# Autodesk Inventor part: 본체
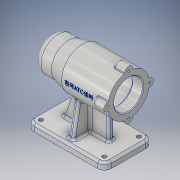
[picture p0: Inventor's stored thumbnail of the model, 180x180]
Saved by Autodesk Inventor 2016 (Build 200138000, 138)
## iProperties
Created: 2019-07
Part Number: 본체
Material: 알루미늄 6061
Document SubType Name: Modeling
Designer: 605-06
Density: 2.7 g/cm^3
Appearance: 알루미늄 - 평지
Mass: 644.654 g
Surface Area: 654.647 cm^2
Volume: 238.761 cm^3
Author: 605-06
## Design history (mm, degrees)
sketch "스케치1"
  geometry: L1 (0, 30)-(67, 30); L2 (67, 30)-(87, 25); L3 (87, 25)-(102, 25); L4 (112, 15)-(112, 0); L5 (112, 0)-(106, 0); L6 (106, 0)-(106, 7.5); L7 (103, 10.5)-(103, 10.5); L8 (103, 10.5)-(103, 15.7); L9 (102.7, 16)-(99, 16); L10 (99, 16)-(99, 17.2); L11 (98.7, 17.5)-(81, 17.5); L12 (81, 17.5)-(81, 20.7); L13 (80.7, 21)-(69, 21); L14 (69, 21)-(69, 21); L15 (66, 24)-(18, 24); L16 (15, 21)-(15, 21); L17 (15, 21)-(1, 21); L18 (0, 22)-(0, 30); L19 (157.163, 0)-(-72.767, 0); L20 (1, 21)-(0, 22); A1 r 3 centre (103, 7.5) between (106, 7.5) and (103, 10.5); A2 r 0.3 centre (102.7, 15.7) between (103, 15.7) and (102.7, 16); A3 r 0.3 centre (98.7, 17.2) between (99, 17.2) and (98.7, 17.5); A4 r 0.3 centre (80.7, 20.7) between (81, 20.7) and (80.7, 21); A5 r 3 centre (66, 21) between (69, 21) and (66, 24); A6 r 3 centre (18, 21) between (18, 24) and (15, 21); A7 r 10 centre (102, 15) between (112, 15) and (102, 25); 2 further points
  constraints: 40 end point, 14 point on circle, 14 tangent, 13 perpendicular, 7 centre point, 3 equal radius, 2 horizontal, 2 horizontal alignment, 2 point on line, 2 vertical, 1 parallel, 1 vertical alignment
  dimensions: "d0" = 112 distance between parallel lines of L4 L18; "d2" = 42 diameter of L17 L19; "d3" = 15 distance between parallel lines of L18 L16; "d4" = 48 diameter of L15 L19; "d5" = 54 distance between parallel lines of L16 L14; "d6" = 42 diameter of L13 L19; "d7" = 12 distance between parallel lines of L14 L12; "d8" = 18 distance between parallel lines of L12 L10; "d9" = 4 distance between parallel lines of L10 L8; "d10" = 3 distance between parallel lines of L8 L6; "d11" = 21 diameter of L7 L19; "d12" = 32 diameter of L9 L19; "d13" = 35 diameter of L11 L19; "d14" = 50 diameter of L3 L19; "d15" = 60 diameter of L1 L19; "d16" = 3 radius of A1; "d17" = 0.3 radius of A2; "d18" = 25 distance from line of L2.end L4; "d19" = 45 distance from line of L1.end L4; "d20" = 1 distance of L17.end point (0, 21); "d21" = 45 deg angle of L17 L20; "d22" = 3 radius of A5; "d23" = 10 radius of A7
revolve "회전1" sketch "스케치1" stored, may be unused: angle "d24" = 90 deg
node "작업 평면1"
sketch "스케치2"
  geometry: L1 (-10, -35)-(-102, -35); L2 (-112, -25)-(-112, 25); L3 (-102, 35)-(-10, 35); L4 (0, 25)-(0, -25); L5 (0, 0)-(-89.179, 0); C1 r 3 at (-102, 25); C2 r 3 at (-102, -25); C3 r 3 at (-10, 25); C4 r 3 at (-10, -25); A1 r 10 centre (-102, -25) between (-112, -25) and (-102, -35); A2 r 10 centre (-102, 25) between (-102, 35) and (-112, 25); A3 r 10 centre (-10, 25) between (0, 25) and (-10, 35); A4 r 10 centre (-10, -25) between (-10, -35) and (0, -25); 1 further point
  constraints: 10 end point, 8 centre point, 8 point on circle, 8 tangent, 4 coincident, 3 equal radius, 2 horizontal, 2 parallel, 2 point on line, 1 perpendicular, 1 vertical alignment
  dimensions: "d26" = 35 distance between parallel lines of L3 L5; "d27" = 70 distance between parallel lines of L1 L3; "d28" = 112 distance between parallel lines of L4 L2; "d29" = 10 radius of A1; "d30" = 6 diameter of C1; "d31" = 6 diameter of C2; "d32" = 6 diameter of C3; "d33" = 6 diameter of C4
extrude "돌출1" join sketch "스케치2" distance "d34" = 10; taper "d35" = 0 deg
sketch "스케치3"
  geometry: L1 (25, -26.691)-(25, -70); L2 (10, -70)-(102, -70) reference; L3 (92, -70)-(76.52, -27.468); L4 (0, -80)-(0, -70) reference; L5 (112, -80)-(112, -70) reference; L6 (112, -70)-(102, -70) reference; L7 (25, -26.691)-(65.86, -26.691); L8 (65.86, -26.691)-(75.023, -23.356); L9 (75.023, -23.356)-(76.52, -27.468); L10 (92, -70)-(25, -70); 1 further point
  constraints: 12 end point, 2 point on line, 1 collinear, 1 horizontal, 1 perpendicular, 1 vertical
  dimensions: "d36" = 25 distance between parallel lines of L4 L1; "d37" = 20 distance from line of L5 L3.start; "d38" = 110 deg angle of L6 L3
extrude "돌출2" join sketch "스케치3" stored distance "d39" = 8; taper "d40" = 0 deg
node "작업 평면2"
sketch "스케치4"
  geometry: L1 (35, -70)-(25, -70) reference; L2 (28, -70)-(19.547, -22.061); L3 (35, -80)-(35, -70) reference; L4 (-28, -70)-(-19.278, -20.537); L5 (-35, -80)-(-35, -70) reference; L6 (-25, -70)-(-35, -70) reference; L7 (-28, -70)-(28, -70); L8 (28, -80)-(28, -70) reference; 1 further point
  constraints: 6 end point, 2 point on line, 1 perpendicular
  dimensions: "d42" = 7 distance from line of L3 L2.start; "d43" = 100 deg angle of L1 L2; "d44" = 7 distance from line of L5 L4.start; "d45" = 100 deg angle of L4 L6
feature "리브1" sketch "스케치4" dims "d46" = 1, "d47" = 8, "d48" = 0, "d49" = 0, "d50" = 1, "d51" = 1
chamfer "모따기1" distance "d52" = 3; stored, may be unused: second distance "d53" = 2, angle "d54" = 45 deg
sketch "스케치5"
  geometry: C1 r 6 at (-30, 0); C2 r 6 at (0, 30); C3 r 6 at (30, 0); C4 r 6 at (0, -30); A1 r 30 centre (0, 0) between (29.732, 4) and (29.732, -4) reference; A2 r 30 centre (0, 0) between (29.732, -4) and (29.732, 4) reference; 3 further points
  constraints: 6 point on circle, 4 centre point, 3 horizontal alignment, 2 vertical alignment
  dimensions: "d55" = 12 diameter of C1; "d56" = 12 diameter of C2; "d57" = 12 diameter of C3; "d58" = 12 diameter of C4
extrude "돌출3" join sketch "스케치5" distance "d59" = 16; taper "d60" = 0 deg
fillet "모깎기1" dims "d61" = 1, "d62" = 3
sketch "스케치6"
  geometry: A1 r 6 centre (-60, 0) between (-60.171, 5.998) and (-60.171, -5.998) reference; A2 r 6 centre (-30, 30) between (-24.002, 30.171) and (-35.998, 30.171) reference; A3 r 6 centre (0, 0) between (0.171, -5.998) and (0.171, 5.998) reference; A4 r 6 centre (-30, -30) between (-35.998, -30.171) and (-24.002, -30.171) reference; 5 further points
  constraints: 4 coincident
hole "구멍1" sketch "스케치6" at (-60, 0), (-30, 30), (0, 0), (-30, -30) diameter "d63" = 3.242; stored, may be unused: countersink angle "d67" = 90 deg, drill point angle "d69" = 118 deg; dims "d64" = 8, "d65" = 4, "d66" = 2, "d68" = 11
node "작업 평면3"
sketch "스케치7"
  geometry: L1 (33.5, 29.226)-(33.5, 6.771) reference; L2 (33.5, 5.998)-(33.5, -5.998) reference; 3 further points
  constraints: 1 horizontal alignment, 1 midpoint, 1 other
  dimensions: "d70" = 42 distance from line of point (-8.5, 0) L1
feature "엠보싱1" sketch "스케치7" dims "d0" = 112, "d2" = 42, "d3" = 15, "d4" = 48, "d5" = 54, "d6" = 42, "d7" = 12, "d8" = 18, "d9" = 4, "d10" = 3, "d11" = 21, "d12" = 32, "d13" = 35, "d14" = 50, "d15" = 60, "d16" = 3, "d17" = 0.3, "d18" = 25, "d19" = 45, "d20" = 1, "d21" = 45 deg, "d22" = 3, "d23" = 10, "d71" = 0.5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
node "솔리드1"
other parameters: "d41" = -56
